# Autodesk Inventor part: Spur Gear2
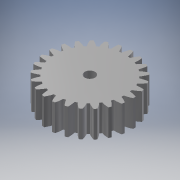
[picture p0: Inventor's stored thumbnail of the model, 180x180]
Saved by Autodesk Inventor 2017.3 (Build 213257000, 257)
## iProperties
Created: 2020-03
Part Number: Spur Gear2
Material: Steel
Document SubType Name: Modeling
Designer: Tim_G
Categories: <?xml version="1.0" encoding="UTF-16"?> <MemberInstance><Categories><FamilyTemplate><FamilyTemplateParameter ValueType="xs:double" Id="1" ObjectReferenceKey="da
Density: 1 g/cm^3
Appearance: Steel
CustomPartVersion: 1
Author: Tim_G
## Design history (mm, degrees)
sketch "Sketch1"
  geometry: C1 r 20.56 at (0, 0)
  constraints: 1 centre point
  dimensions: "d0" = 41.11927 diameter of C1 (= da_da)
extrude "Extrusion1" new body sketch "Sketch1" distance "d1" = 13 (= da_b); taper "d2" = 0 deg
workplane "Work Plane2"
sketch "Sketch2"
  geometry: C1 r 20.56 at (0, 0) reference; C2 r 19.037 at (0, 0)
  constraints: 1 centre point, 1 coincident
  dimensions: "d3" = 38.07339 diameter of C2 (= da_dw)
feature "Pitch Diameter" sketch "Sketch2" dims "d4" = 10, "d5" = 0
workplane "Work Plane8"
workplane "Work Plane9"
feature "Spur Gear" dims "da_b" = 13, "da_d" = 38.07339, "da_aw" = 28.17431, "da_da" = 41.11927, "da_df" = 34.26606, "da_dw" = 38.07339, angle "da_beta" = 0 deg, "da_lefttooth" = 0, "da_righttooth" = 0
sketch "Sketch3"
  geometry: C1 r 2.5 at (0, 0); 1 further point
  constraints: 1 centre point, 1 coincident
  dimensions: "d49" = 5 diameter of C1
extrude "Extrusion2" cut sketch "Sketch3" distance "d50" = 13; taper "d51" = 0 deg
body "Solid1"
body "Srf1"
other parameters: "d16" = 28.17431 (= da_aw), "d17" = 0, "d34" = 1.25664 (computed from da_z), "d39" = 0, "d41" = 0, "d43" = 28.17431 (= da_aw), "d46" = 28.17431 (= da_aw), "d47" = 0, "d48" = 0
